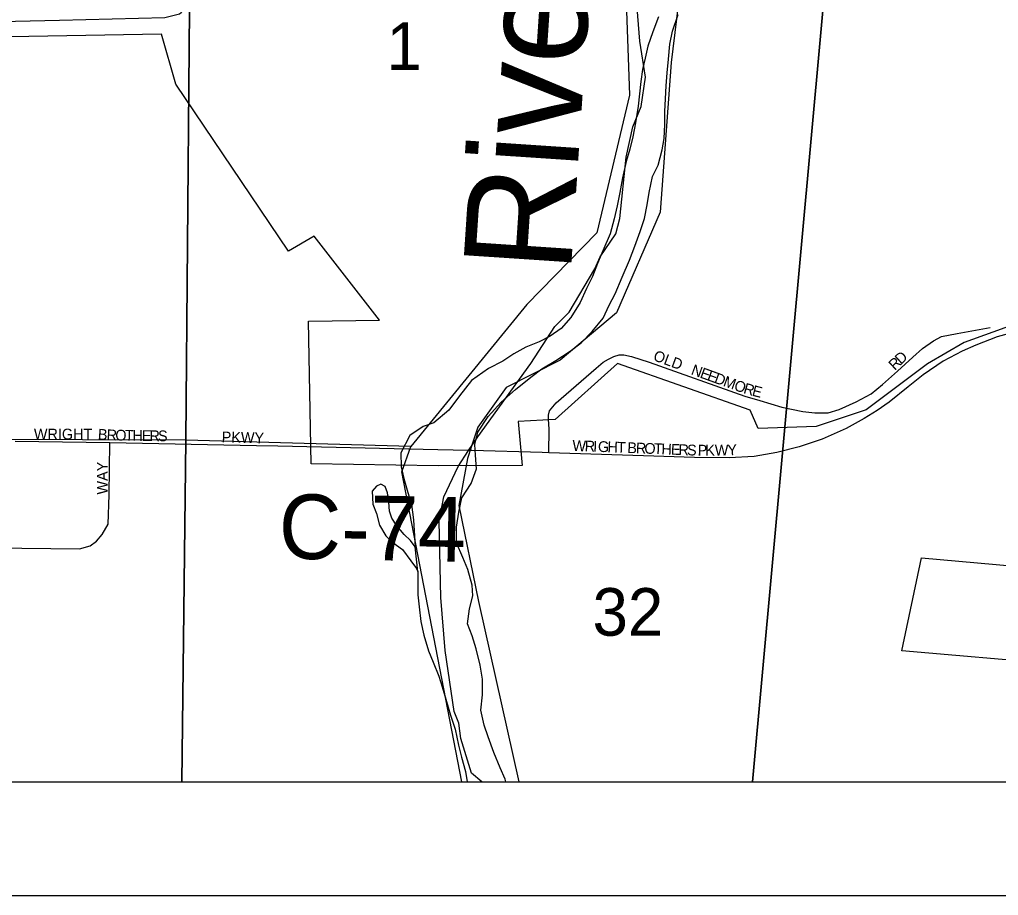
# Model space of a CAD drawing. Extents: x 8.5 to 81.5, y -1.2 to 22.4.
# Drawn here: x 54.054 to 54.915, y 14.351 to 15.121 of the extents above; entities that cross this region are included whole.
import ezdxf

# ---------------------------------------------------------------- set-up
doc = ezdxf.new("R2010")
doc.units = 0
for name, color, linetype in [('GM_X_City_Street', 7, 'Continuous'), ('GM_X_City_Street_Text', 7, 'Continuous'), ('GM_X_Corporation', 7, 'Continuous'), ('GM_X_County', 7, 'Continuous'), ('GM_X_County_Road', 7, 'Continuous'), ('GM_X_County_Road_Text', 7, 'Continuous'), ('GM_X_Major_River', 7, 'Continuous'), ('GM_X_Major_River_Text', 7, 'Continuous'), ('GM_X_Section', 7, 'Continuous'), ('GM_X_Section_Text', 7, 'Continuous'), ('GM_X_Township', 7, 'Continuous'), ('GM_X_Township_Subdivision', 7, 'Continuous'), ('SH_Data', 7, 'Continuous')]:
    doc.layers.add(name, color=color, linetype=linetype)

msp = doc.modelspace()

# ---------------------------------------------------------------- linework, layer by layer
at = {"layer": 'GM_X_City_Street'}
for points in [[(54.5194, 14.73971), (54.51945, 14.76052), (54.51895, 14.76928), (54.51905, 14.7727), (54.51992, 14.77648), (54.52583, 14.78354), (54.56091, 14.81411), (54.56714, 14.81926), (54.57178, 14.82217), (54.57641, 14.82433), (54.58101, 14.82571), (54.58519, 14.82598), (54.59199, 14.82427), (54.60741, 14.81926), (54.69165, 14.78951), (54.70483, 14.78571), (54.72404, 14.77984), (54.74254, 14.77589), (54.75314, 14.77484), (54.76493, 14.77488), (54.77451, 14.77765), (54.78952, 14.78445), (54.80265, 14.79169), (54.81276, 14.79977), (54.82602, 14.81157), (54.8393, 14.82374), (54.84788, 14.83149), (54.85757, 14.83806), (54.86453, 14.84205), (54.87828, 14.8447), (54.90731, 14.84997)], [(54.92749, 14.84543), (54.91358, 14.84169), (54.89478, 14.83424), (54.88273, 14.82893), (54.8661, 14.82018), (54.84845, 14.80828), (54.83525, 14.79781), (54.81861, 14.78417), (54.80814, 14.777), (54.79652, 14.76983), (54.78089, 14.76108), (54.75952, 14.75161), (54.73929, 14.74502), (54.71993, 14.74007), (54.69999, 14.73655), (54.67775, 14.73541), (54.64749, 14.73555), (54.60259, 14.73713), (54.5194, 14.73971), (54.51337, 14.74), (54.45169, 14.74163)], [(53.94262, 14.75104), (53.94291, 14.69261), (53.94247, 14.68064), (53.94602, 14.67132), (53.95222, 14.66378), (53.95799, 14.66024), (53.96642, 14.65713), (53.97972, 14.65669), (54.10654, 14.65536), (54.11585, 14.65802), (54.12162, 14.66201), (54.1265, 14.66777), (54.13182, 14.67709), (54.13271, 14.70281), (54.13325, 14.74846)], [(54.28098, 14.74542), (54.26219, 14.74582), (54.13325, 14.74846), (54.05, 14.74972)], [(54.45169, 14.74163), (54.44854, 14.74172), (54.42171, 14.74244), (54.42157, 14.74244)]]:
    msp.add_lwpolyline(points, dxfattribs=at)
at = {"layer": 'GM_X_Corporation'}
for points in [[(54.92756, 14.85219), (54.8846, 14.83655), (54.8522, 14.81799), (54.79834, 14.77753), (54.75442, 14.76274), (54.70331, 14.76095), (54.69647, 14.77709), (54.57957, 14.81823), (54.52486, 14.76892), (54.49223, 14.7672), (54.4957, 14.72859), (54.42196, 14.72819), (54.31015, 14.72988), (54.30798, 14.85533), (54.37047, 14.85644), (54.31287, 14.9302), (54.29024, 14.91712), (54.19133, 15.06384), (54.1787, 15.10791), (53.99501, 15.10468)], [(54.92756, 14.85219), (54.8846, 14.83655), (54.8522, 14.81799), (54.79834, 14.77753), (54.75442, 14.76274), (54.70331, 14.76095), (54.69647, 14.77709), (54.57957, 14.81823), (54.52486, 14.76892), (54.49223, 14.7672), (54.4957, 14.72859), (54.42196, 14.72819), (54.31015, 14.72988), (54.30798, 14.85533), (54.37047, 14.85644), (54.31287, 14.9302), (54.29024, 14.91712), (54.19133, 15.06384), (54.1787, 15.10791), (53.99501, 15.10468)], [(53.19884, 14.45055), (56.25272, 14.45055), (56.25272, 14.729)], [(54.96543, 14.55379), (54.82959, 14.56567), (54.84692, 14.64726), (54.96198, 14.63721)], [(54.96543, 14.55379), (54.82959, 14.56567), (54.84692, 14.64726), (54.96198, 14.63721)]]:
    msp.add_lwpolyline(points, dxfattribs=at)
at = {"layer": 'GM_X_County'}
msp.add_lwpolyline([(54.08792, 21.25055), (49.45272, 21.25055), (49.45272, 14.45055), (56.25272, 14.45055), (56.25272, 19.11082)], dxfattribs=at)
at = {"layer": 'GM_X_County_Road'}
msp.add_lwpolyline([(54.42157, 14.74244), (54.28098, 14.74542)], dxfattribs=at)
at = {"layer": 'GM_X_Major_River'}
msp.add_line((54.40401, 14.63549), (54.40164, 14.65717), dxfattribs=at)
for points in [[(54.48144, 14.45055), (54.48078, 14.45279), (54.47642, 14.46278), (54.47099, 14.4762), (54.46594, 14.49), (54.46235, 14.50035), (54.45956, 14.51334), (54.46098, 14.527), (54.46087, 14.5407), (54.45883, 14.55292), (54.45532, 14.56744), (54.45175, 14.57893), (54.44778, 14.58928), (54.44956, 14.60256), (54.45244, 14.61392), (54.45187, 14.62344), (54.44797, 14.63721), (54.44361, 14.64757), (54.43817, 14.66061), (54.43807, 14.67431), (54.44023, 14.68758), (54.44276, 14.70008), (54.45099, 14.71285), (54.4558, 14.72568), (54.45489, 14.73749), (54.45432, 14.74701), (54.45682, 14.75799), (54.46583, 14.7715), (54.47748, 14.7842), (54.48985, 14.79536), (54.50336, 14.80612), (54.513, 14.81353), (54.52531, 14.82089), (54.538, 14.829), (54.54765, 14.83641), (54.55734, 14.84648), (54.56707, 14.85808), (54.57223, 14.86938), (54.57775, 14.87954), (54.58374, 14.89425), (54.59011, 14.90895), (54.59492, 14.92141), (54.59973, 14.93424), (54.60337, 14.94558), (54.60589, 14.95769), (54.60763, 14.96869), (54.61056, 14.9827), (54.61532, 14.99249), (54.61901, 15.0061), (54.62072, 15.01596), (54.62135, 15.02849), (54.62119, 15.0399), (54.62179, 15.05092), (54.6224, 15.06231), (54.62338, 15.0737), (54.62438, 15.08585), (54.62578, 15.09913), (54.62791, 15.11049), (54.63314, 15.12521)], [(54.61562, 15.12291), (54.6108, 15.1097), (54.60637, 15.09724), (54.60388, 15.08664), (54.60179, 15.0768), (54.60006, 15.06619), (54.59908, 15.05518), (54.59773, 15.04456), (54.59554, 15.02977), (54.59302, 15.01766), (54.59053, 15.00668), (54.58727, 14.99572), (54.58395, 14.98133), (54.58179, 14.96845), (54.57928, 14.95671), (54.57678, 14.94535), (54.5731, 14.93212), (54.56673, 14.91741), (54.56194, 14.9061), (54.55754, 14.89478), (54.55239, 14.88424), (54.54683, 14.8718), (54.53859, 14.85865), (54.53004, 14.84894), (54.52041, 14.84229), (54.51081, 14.83716), (54.49894, 14.83245), (54.48857, 14.82658), (54.47895, 14.8203), (54.46628, 14.81371), (54.45126, 14.80337), (54.44074, 14.78989), (54.43137, 14.77714), (54.41823, 14.766), (54.40867, 14.76277), (54.39712, 14.75502), (54.38922, 14.73958), (54.38936, 14.72741), (54.39181, 14.71709), (54.39537, 14.70484), (54.39857, 14.69413), (54.40021, 14.68078), (54.40164, 14.65717)], [(54.40164, 14.65717), (54.39757, 14.66258), (54.39198, 14.66802), (54.38567, 14.67537), (54.38124, 14.68231), (54.37909, 14.68844), (54.37849, 14.69644), (54.3775, 14.70444), (54.37534, 14.7102), (54.37158, 14.71217), (54.36774, 14.71035), (54.36386, 14.70586), (54.36439, 14.69444), (54.36765, 14.68638), (54.37048, 14.67606), (54.376, 14.66682), (54.38196, 14.66099), (54.39057, 14.65473), (54.39797, 14.64469), (54.40278, 14.63813), (54.40401, 14.63549)], [(54.40401, 14.63549), (54.40422, 14.61489), (54.40515, 14.60422), (54.40679, 14.59125), (54.40921, 14.57941), (54.4135, 14.56563), (54.41748, 14.55566), (54.42256, 14.54338), (54.4254, 14.53381), (54.42861, 14.5231), (54.43289, 14.50893), (54.43682, 14.49668), (54.43996, 14.48254), (54.44242, 14.47221), (54.44596, 14.45959), (54.44744, 14.45055)]]:
    msp.add_lwpolyline(points, dxfattribs=at)
at = {"layer": 'GM_X_Section'}
for p, q in [((53.19847, 14.45055), (54.19651, 14.45055)), ((54.19651, 14.45055), (54.44278, 14.45055)), ((54.49285, 14.45055), (54.69845, 14.45055)), ((54.69845, 14.45055), (55.67571, 14.45055))]:
    msp.add_line(p, q, dxfattribs=at)
for points in [[(53.20654, 15.7628), (53.38111, 15.76219), (53.37065, 15.64839), (53.39983, 15.52779), (53.43828, 15.39679), (53.48653, 15.28416), (53.59159, 15.17085), (53.6755, 15.14163), (53.76095, 15.13435), (53.82912, 15.15428), (53.87117, 15.19553), (53.9105, 15.25312), (53.94312, 15.29606), (54.00622, 15.34903), (54.08999, 15.39329), (54.206, 15.44035), (54.19991, 14.75082), (53.19976, 14.75402)], [(54.19991, 14.75082), (54.206, 15.44035), (54.29187, 15.45503), (54.51292, 15.42816), (54.57195, 15.26383), (54.58759, 15.12833), (54.59036, 15.05405), (54.56158, 14.93302), (54.49981, 14.87017), (54.39787, 14.74521)]]:
    msp.add_lwpolyline(points, close=True, dxfattribs=at)
for points in [[(54.69845, 14.45055), (54.76697, 15.20261), (54.63198, 15.21347), (54.63628, 15.15999), (54.62688, 15.08291), (54.61722, 14.9513), (54.57882, 14.86263), (54.52919, 14.82115), (54.48178, 14.79704), (54.45689, 14.76229), (54.45088, 14.7446), (54.44766, 14.73482), (54.44007, 14.6933), (54.45743, 14.6089), (54.49285, 14.45055)], [(55.67571, 14.45055), (55.74333, 15.12296), (54.76697, 15.20261), (54.69845, 14.45055)], [(54.19651, 14.45055), (54.19991, 14.75082), (53.19976, 14.75402), (53.19847, 14.45055)], [(54.44278, 14.45055), (54.38988, 14.72302), (54.39787, 14.74521), (54.19991, 14.75082), (54.19651, 14.45055)]]:
    msp.add_lwpolyline(points, dxfattribs=at)
at = {"layer": 'GM_X_Township'}
for points in [[(49.45272, 15.76006), (49.45272, 14.45055), (54.46023, 14.45055)], [(54.46023, 14.45055), (54.45126, 14.45814), (54.44199, 14.48859), (54.44019, 14.50191), (54.43609, 14.51219), (54.42813, 14.56583), (54.42428, 14.6126), (54.42286, 14.6795), (54.4268, 14.70114), (54.4395, 14.72768), (54.44854, 14.74172), (54.45674, 14.75382), (54.50345, 14.81819), (54.52453, 14.85076), (54.53713, 14.86324), (54.55977, 14.90151), (54.56439, 14.91212), (54.57818, 14.93219), (54.58169, 14.94585), (54.58737, 14.99978), (54.59324, 15.02634), (54.60057, 15.04416), (54.60416, 15.06998), (54.59945, 15.10153), (54.59562, 15.1498)]]:
    msp.add_lwpolyline(points, dxfattribs=at)
at = {"layer": 'GM_X_Township_Subdivision'}
msp.add_lwpolyline([(53.99653, 15.11807), (53.9983, 15.11811), (54.08896, 15.12022), (54.18173, 15.12236), (54.19438, 15.12553), (54.19588, 15.12689), (54.19863, 15.12935)], dxfattribs=at)
at = {"layer": 'SH_Data'}
for p, q in [((49.45272, 14.45055), (56.25272, 14.45055)), ((49.35272, 14.35055), (56.35272, 14.35055))]:
    msp.add_line(p, q, dxfattribs=at)

# ---------------------------------------------------------------- texts
at = {"layer": 'GM_X_City_Street_Text'}
for s, rotation, p in [('OLD', 339.68029, (54.6104, 14.82134)), ('D', 42.91322, (54.82892, 14.81684)), ('N', 340.12708, (54.64372, 14.80885)), ('R', 43.19667, (54.82346, 14.81171)), ('E', 340.12528, (54.65156, 14.80602)), ('E', 340.14186, (54.65783, 14.80375)), ('D', 340.13451, (54.6641, 14.80148)), ('M', 340.1367, (54.67194, 14.79865)), ('O', 340.24692, (54.68137, 14.79525)), ('R', 343.78297, (54.68981, 14.79223)), ('E', 345.85158, (54.69738, 14.79004)), ('WRIGHT', 0.00001, (54.06645, 14.75145)), ('B', 355.72235, (54.12242, 14.75145)), ('R', 357.60517, (54.13024, 14.75087)), ('O', 358.97938, (54.13798, 14.75055)), ('T', 359.05283, (54.14633, 14.7504)), ('H', 359.03824, (54.15299, 14.75029)), ('E', 359.0665, (54.16133, 14.75015)), ('R', 359.06778, (54.168, 14.75004)), ('S', 359.04379, (54.17549, 14.74992)), ('PKWY', 358.6036, (54.23149, 14.74895)), ('W', 357.77995, (54.53985, 14.74145)), ('R', 357.79622, (54.55068, 14.74103)), ('I', 357.77053, (54.55817, 14.74074)), ('G', 357.79735, (54.56234, 14.74058)), ('H', 357.79152, (54.57067, 14.74026)), ('T', 357.78115, (54.579, 14.73994)), ('B', 357.79622, (54.58816, 14.73958)), ('R', 357.78994, (54.59566, 14.73929)), ('O', 357.786, (54.60315, 14.739)), ('T', 357.78115, (54.61148, 14.73868)), ('H', 357.786, (54.61814, 14.73843)), ('E', 357.78115, (54.62646, 14.73811)), ('R', 357.76567, (54.63312, 14.73785)), ('S', 358.20965, (54.6407, 14.73755)), ('P', 359.83244, (54.65015, 14.73731)), ('K', 0.06037, (54.65686, 14.73729)), ('W', 0.27113, (54.66523, 14.7373)), ('Y', 3.4563, (54.67664, 14.73737)), ('WAY', 90, (54.13133, 14.70301))]:
    msp.add_text(s, height=0.00947, rotation=rotation, dxfattribs=at).set_placement(p)
at = {"layer": 'GM_X_County_Road_Text'}
msp.add_text('C-74', height=0.056818, rotation=358.97141, dxfattribs=at).set_placement((54.28134, 14.6468))
at = {"layer": 'GM_X_Major_River_Text'}
msp.add_text('River', height=0.094745, rotation=86.19646, dxfattribs=at).set_placement((54.53848, 14.89681))
at = {"layer": 'GM_X_Section_Text'}
for s, height, p in [('1', 0.04186, (54.37645, 15.0764)), ('32', 0.041856, (54.5577, 14.5789))]:
    msp.add_text(s, height=height, rotation=0.00001, dxfattribs=at).set_placement(p)

doc.saveas('drawing.dxf')
